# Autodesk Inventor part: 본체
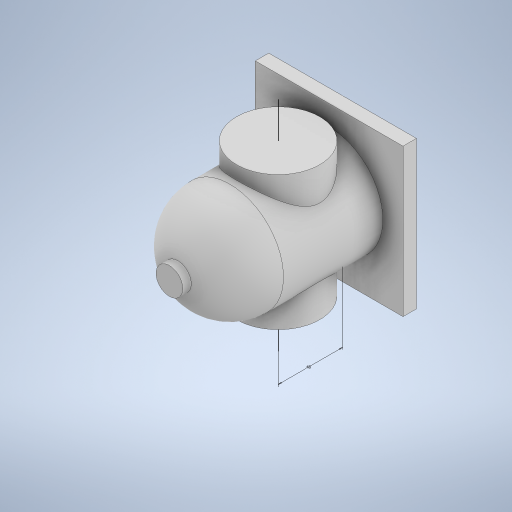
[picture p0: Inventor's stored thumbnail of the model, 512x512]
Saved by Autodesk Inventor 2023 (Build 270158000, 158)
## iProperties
Created: 2025-04
Part Number: 본체
Material: 일반
Document SubType Name: Modeling
Designer: ADMIN_PC
Density: 1 g/cm^3
Appearance: 기본값
Author: ADMIN_PC
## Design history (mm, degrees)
sketch "스케치1"
  geometry: C1 r 40 at (0, 0); 1 further point
  constraints: 1 centre point, 1 coincident
  dimensions: "d0" = 80 diameter of C1
extrude "돌출1" new body sketch "스케치1" stored distance "d1" = 84; taper "d2" = 0 deg
sketch "스케치2"
  geometry: L1 (55, 55)-(-55, 55); L2 (-55, 55)-(-55, -55); L3 (-55, -55)-(55, -55); L4 (55, -55)-(55, 55); L5 (55, 55)-(-55, -55); L6 (-55, 55)-(55, -55); 1 further point
  constraints: 12 end point, 2 midpoint, 2 parallel, 1 horizontal, 1 perpendicular
  dimensions: "d3" = 110 distance of L3.end L2.end; "d4" = 110 distance of L2.end L1.end
extrude "돌출2" join sketch "스케치2" distance "d5" = 10; taper "d6" = 0 deg
sketch "스케치4"
  geometry: C1 r 10 at (0, 0); 1 further point
  constraints: 1 centre point, 1 coincident
  dimensions: "d9" = 20 diameter of C1
extrude "돌출3" join sketch "스케치4" distance "d10" = 45; taper "d11" = 0 deg
sketch "스케치3"
  geometry: L1 (77, 0)-(-77, 0) reference; L2 (0, -58.8)-(0, 58.8) reference; L3 (40, 42)-(-40, 42) reference; L4 (40, 42)-(0, 42); L5 (0, 42)-(0, 82); A1 r 40 centre (0, 42) between (40, 42) and (0, 82); 1 further point
  constraints: 4 end point, 2 point on circle, 1 centre point, 1 collinear, 1 midpoint, 1 perpendicular, 1 point on line
  dimensions: "d8" = 40 radius of A1
revolve "회전1" sketch "스케치3" stored, may be unused: angle "d12" = 90 deg
sketch "스케치8"
  geometry: L1 (-55, -42)-(55, -42) reference; L2 (0, -67.8)-(0, 112.8) reference; C1 r 31 at (0, 6)
  constraints: 1 centre point, 1 point on line
  dimensions: "d14" = 62 diameter of C1; "d17" = 48 distance from line of L1 C1.centre
extrude "돌출4" join sketch "스케치8" stored distance "d15" = 100; taper "d16" = 0 deg
sketch "스케치9"
  geometry: L1 (76.691, 6)-(-85.662, 6); L2 (55, -42)-(-55, -42) reference; 1 further point
  constraints: 2 end point, 1 horizontal
  dimensions: "d19" = 48 distance between parallel lines of L2 L1
node "솔리드1"
